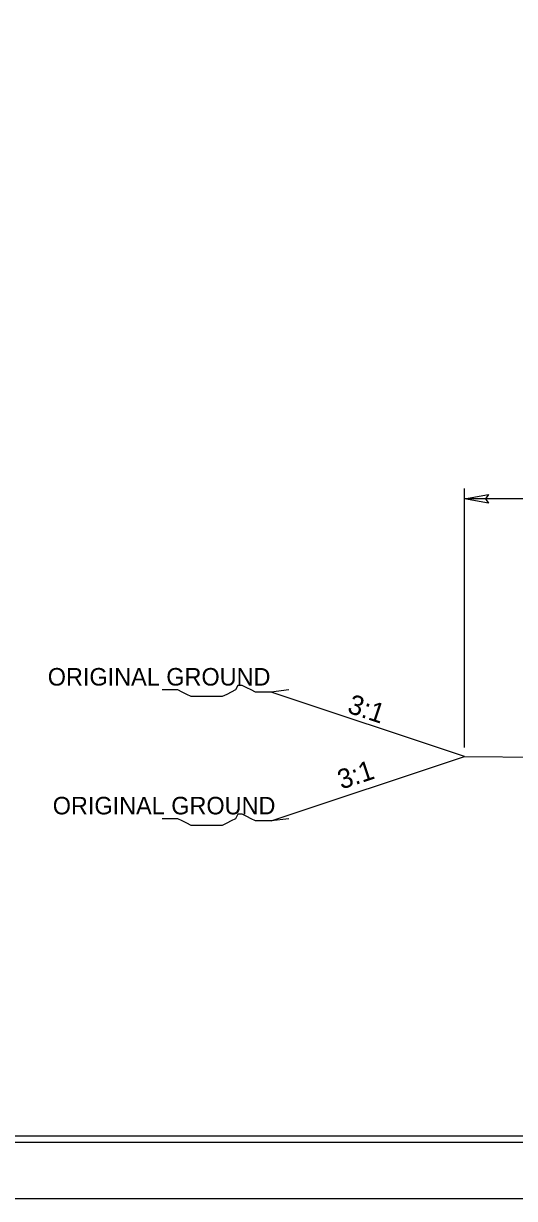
# Model space of a CAD drawing. Extents: x 958711 to 962106, y 831169 to 840840.
# Drawn here: x 959176.2 to 959372.3, y 834842.4 to 835311.7 of the extents above; entities that cross this region are included whole.
import ezdxf

# ---------------------------------------------------------------- set-up
doc = ezdxf.new("R2010")
doc.units = 0
for name, color, linetype in [('Old_Level_1', 7, 'Continuous'), ('Old_Level_11', 7, 'Continuous'), ('Old_Level_21', 7, 'Continuous'), ('Old_Level_3', 7, 'Continuous'), ('Sheet Plot Border Inside CELL', 7, 'Continuous'), ('Sheet Plot Border Outside CELL', 7, 'Continuous'), ('Sheet Typical CELL', 7, 'Continuous')]:
    doc.layers.add(name, color=color, linetype=linetype)

msp = doc.modelspace()

# ---------------------------------------------------------------- linework, layer by layer
at = {"layer": 'Old_Level_1'}
for p, q in [((959352.27, 835022.62), (959352.27, 835126.07)), ((959418.82, 835121.85), (959352.27, 835121.85)), ((959352.27, 835018.94), (959275.08, 835044.67)), ((959275.08, 834993.2), (959352.27, 835018.94)), ((959352.27, 835018.94), (959415.26, 835018.3))]:
    msp.add_line(p, q, dxfattribs=at)
at = {"layer": 'Old_Level_11'}
msp.add_lwpolyline([(959361.88, 835120.2), (959352.27, 835121.85), (959361.93, 835123.56), (959360.71, 835121.85)], close=True, dxfattribs=at)
at = {"layer": 'Old_Level_21'}
for points in [[(959282.18, 835045.55), (959275.08, 835044.67), (959273.31, 835044.67), (959270.65, 835044.67), (959268.87, 835044.67), (959267.1, 835045.55), (959265.32, 835046.44), (959263.56, 835047.33), (959261.78, 835047.33), (959260.88, 835045.55), (959259.12, 835044.67), (959257.34, 835043.77), (959255.57, 835042.9), (959253.8, 835042.9), (959252.03, 835042.9), (959250.25, 835042.9), (959248.48, 835042.9), (959246.7, 835042.9), (959244.93, 835042.9), (959243.16, 835042.9), (959241.39, 835043.77), (959239.62, 835044.67), (959237.85, 835045.55), (959235.17, 835045.55), (959233.4, 835045.55), (959231.63, 835045.55)], [(959282.18, 834994.09), (959275.08, 834993.2), (959273.31, 834993.2), (959270.65, 834993.2), (959268.87, 834993.2), (959267.1, 834994.09), (959265.32, 834994.98), (959263.56, 834995.86), (959261.78, 834995.86), (959260.88, 834994.09), (959259.12, 834993.2), (959257.34, 834992.31), (959255.57, 834991.43), (959253.8, 834991.43), (959252.03, 834991.43), (959250.25, 834991.43), (959248.48, 834991.43), (959246.7, 834991.43), (959244.93, 834991.43), (959243.16, 834991.43), (959241.39, 834992.31), (959239.62, 834993.2), (959237.85, 834994.09), (959235.17, 834994.09), (959233.4, 834994.09), (959231.63, 834994.09)]]:
    msp.add_lwpolyline(points, dxfattribs=at)
at = {"layer": 'Sheet Plot Border Inside CELL'}
msp.add_lwpolyline([(960390.3, 835919.97), (958723.8, 835919.97), (958723.8, 834864.87), (960390.3, 834864.87)], close=True, dxfattribs=at)
at = {"layer": 'Sheet Plot Border Outside CELL'}
msp.add_lwpolyline([(960394.8, 835942.42), (958710.8, 835942.42), (958710.8, 834842.42), (960394.8, 834842.42)], close=True, dxfattribs=at)
at = {"layer": 'Sheet Typical CELL'}
msp.add_lwpolyline([(960377.8, 835917.42), (958877.8, 835917.42), (958877.8, 834867.42), (960377.8, 834867.42)], close=True, dxfattribs=at)

# ---------------------------------------------------------------- texts
at = {"layer": 'Old_Level_21'}
for p in [(959185.88, 835047.3), (959187.87, 834995.84)]:
    msp.add_text('ORIGINAL GROUND', height=7, dxfattribs=at).set_placement(p)
at = {"layer": 'Old_Level_3'}
for rotation, p in [(341.5652, (959305.12, 835036.63)), (18.4348, (959303.15, 835005.72))]:
    msp.add_text('3:1', height=7.801, rotation=rotation, dxfattribs=at).set_placement(p)

doc.saveas('drawing.dxf')
